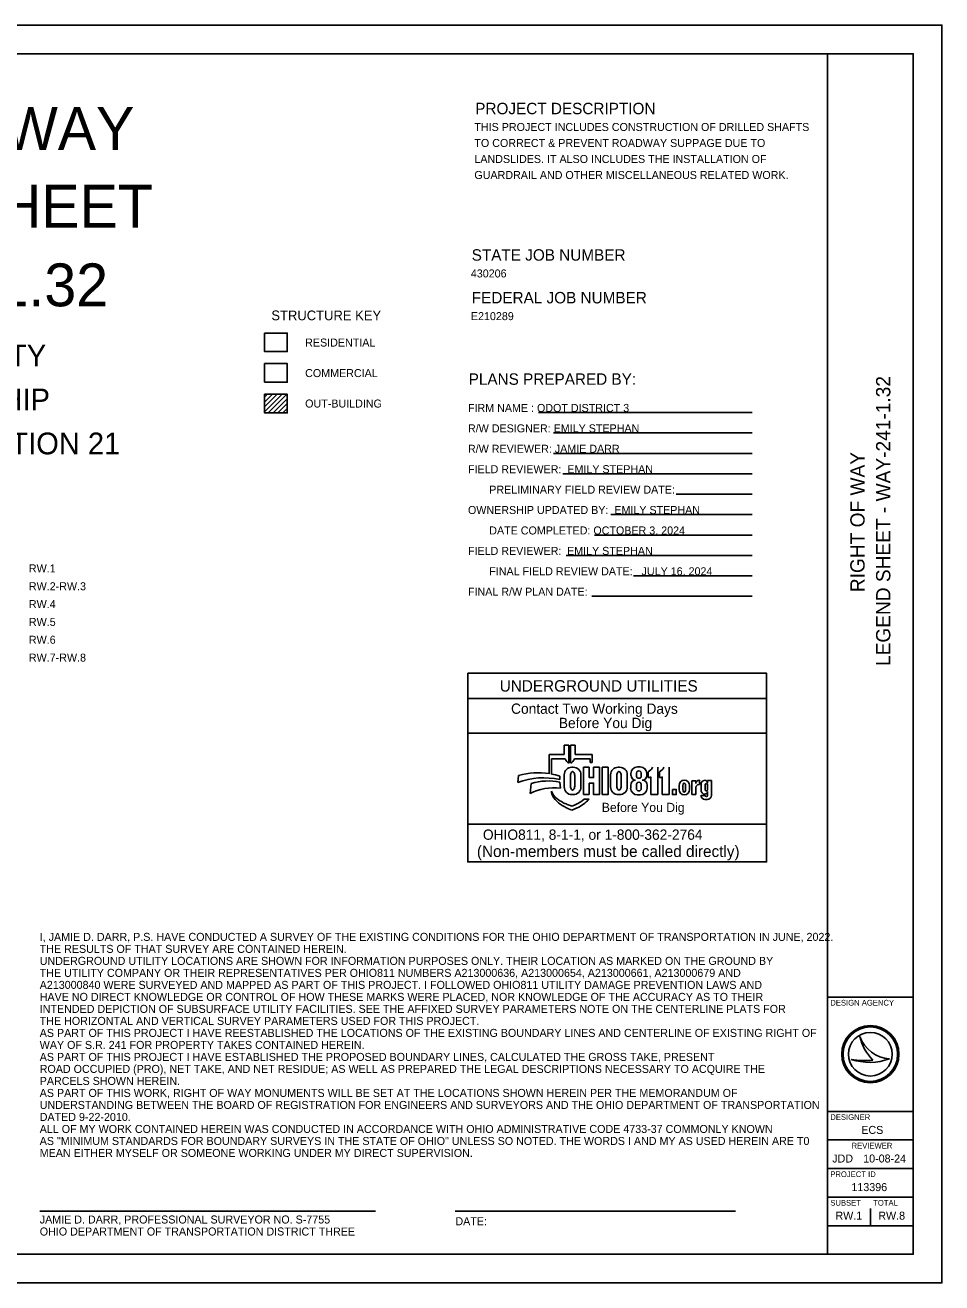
# Model space of a CAD drawing. Extents: x 0 to 34, y 0 to 22.
# Drawn here: x 17.97 to 34, y 0 to 22 of the extents above; entities that cross this region are included whole.
import ezdxf

# ---------------------------------------------------------------- set-up
doc = ezdxf.new("R2010")
doc.units = 0
for name, color, linetype in [('Default', 7, 'Continuous'), ('SC_Shading1', 7, 'Continuous'), ('SH_Border', 7, 'Continuous'), ('SH_Cut_Line', 7, 'Continuous'), ('SH_Data', 7, 'Continuous'), ('SH_Text', 7, 'Continuous')]:
    doc.layers.add(name, color=color, linetype=linetype)

msp = doc.modelspace()

# ---------------------------------------------------------------- linework, layer by layer
at = {"layer": 'Default'}
for p, q in [((18.229, 1.256), (24.096, 1.256)), ((25.492, 1.256), (30.391, 1.256))]:
    msp.add_line(p, q, dxfattribs=at)
at = {"layer": 'SC_Shading1'}
msp.add_lwpolyline([(22.159, 15.753), (22.556, 15.753), (22.556, 16.079), (22.159, 16.079)], close=True, dxfattribs=at)
at = {"layer": 'SH_Border'}
for p, q in [((32, 0.5), (32, 21.5)), ((32, 5), (33.5, 5)), ((32, 3), (33.5, 3)), ((32, 2.5), (33.5, 2.5)), ((32, 2), (33.5, 2)), ((32, 1.5), (33.5, 1.5)), ((32, 1), (33.5, 1))]:
    msp.add_line(p, q, dxfattribs=at)
msp.add_lwpolyline([(1.5, 21.5), (33.5, 21.5), (33.5, 0.5), (1.5, 0.5)], close=True, dxfattribs=at)
at = {"layer": 'SH_Cut_Line'}
msp.add_lwpolyline([(0, 0), (34, 0), (34, 22), (0, 22)], close=True, dxfattribs=at)
at = {"layer": 'SH_Data'}
for p, q in [((27.399, 9.241), (27.136, 9.241)), ((27.136, 9.241), (27.136, 8.906)), ((27.479, 9.407), (27.399, 9.407)), ((27.399, 9.407), (27.399, 9.241)), ((27.479, 9.09), (27.479, 9.407)), ((27.591, 9.407), (27.51, 9.407)), ((27.51, 9.407), (27.51, 9.09)), ((27.591, 9.241), (27.591, 9.407)), ((27.888, 9.241), (27.591, 9.241)), ((27.888, 9.1), (27.888, 9.241)), ((27.174, 8.9), (27.174, 9.164)), ((27.174, 9.164), (27.415, 9.164)), ((27.575, 9.164), (27.853, 9.164)), ((27.853, 9.164), (27.853, 9.1)), ((27.853, 9.1), (27.888, 9.1)), ((28.728, 9.026), (28.679, 9.026)), ((26.601, 8.872), (26.587, 8.755)), ((27.32, 8.804), (27.32, 8.862)), ((27.398, 8.886), (27.398, 8.674)), ((27.507, 8.691), (27.507, 8.873)), ((27.556, 9.019), (27.531, 9.019)), ((27.581, 8.873), (27.581, 8.691)), ((27.69, 8.674), (27.69, 8.886)), ((27.834, 9.018), (27.732, 9.018)), ((27.732, 9.018), (27.732, 8.54)), ((28.209, 8.886), (28.209, 8.674)), ((28.317, 8.691), (28.317, 8.873)), ((28.367, 9.019), (28.342, 9.019)), ((28.392, 8.873), (28.392, 8.691)), ((28.501, 8.674), (28.501, 8.886)), ((28.565, 8.912), (28.565, 8.876)), ((28.664, 8.859), (28.664, 8.917)), ((28.745, 8.917), (28.745, 8.859)), ((28.842, 8.876), (28.842, 8.912)), ((28.865, 8.838), (28.865, 8.939)), ((28.913, 8.54), (28.913, 8.852)), ((29.032, 9.018), (29.032, 8.54)), ((29.065, 8.838), (29.065, 8.939)), ((29.113, 8.54), (29.113, 8.852)), ((29.232, 9.018), (29.232, 8.54)), ((26.822, 8.737), (26.8, 8.557)), ((27.173, 8.6), (27.178, 8.573)), ((27.33, 8.654), (27.321, 8.76)), ((27.834, 8.54), (27.834, 8.742)), ((28.56, 8.706), (28.56, 8.655)), ((28.66, 8.646), (28.66, 8.707)), ((28.745, 8.707), (28.745, 8.646)), ((28.848, 8.655), (28.848, 8.706)), ((29.406, 8.631), (29.406, 8.699)), ((29.473, 8.63), (29.473, 8.699)), ((29.521, 8.699), (29.521, 8.63)), ((29.588, 8.699), (29.588, 8.631)), ((29.701, 8.783), (29.628, 8.783)), ((29.628, 8.783), (29.628, 8.54)), ((29.701, 8.736), (29.701, 8.783)), ((29.701, 8.54), (29.701, 8.667)), ((29.75, 8.717), (29.761, 8.717)), ((29.761, 8.791), (29.755, 8.791)), ((29.761, 8.717), (29.761, 8.791)), ((29.79, 8.618), (29.79, 8.722)), ((29.862, 8.632), (29.862, 8.708)), ((29.904, 8.738), (29.904, 8.785)), ((29.904, 8.785), (29.97, 8.785)), ((29.904, 8.708), (29.904, 8.632)), ((29.904, 8.526), (29.904, 8.596)), ((29.97, 8.785), (29.97, 8.526)), ((27.538, 8.339), (27.449, 8.37)), ((27.531, 8.54), (27.556, 8.54)), ((27.599, 8.366), (27.538, 8.339)), ((27.732, 8.54), (27.834, 8.54)), ((27.832, 8.46), (27.746, 8.46)), ((27.829, 8.457), (27.832, 8.46)), ((28.342, 8.54), (28.367, 8.54)), ((28.68, 8.534), (28.727, 8.534)), ((29.032, 8.54), (28.913, 8.54)), ((29.232, 8.54), (29.113, 8.54)), ((29.628, 8.54), (29.701, 8.54)), ((29.79, 8.526), (29.862, 8.526)), ((29.9, 8.457), (29.859, 8.457)), ((27.473, 8.293), (27.529, 8.269)), ((27.529, 8.269), (27.624, 8.31)), ((30.935, 7.362), (25.71, 7.362)), ((32.567, 4.31), (32.567, 4.31)), ((32.75, 4), (32.75, 4)), ((32.417, 3.91), (32.417, 3.91)), ((33.087, 3.919), (33.087, 3.919)), ((32.75, 1), (32.75, 1.3))]:
    msp.add_line(p, q, dxfattribs=at)
for points in [[(25.71, 10.662), (30.935, 10.662), (30.935, 10.222), (25.71, 10.222)], [(25.71, 10.222), (30.935, 10.222), (30.935, 9.617), (25.71, 9.617)], [(25.71, 9.617), (30.935, 9.617), (30.935, 8.022), (25.71, 8.022)], [(29.29, 8.63), (29.356, 8.63), (29.356, 8.54), (29.29, 8.54)], [(25.71, 8.022), (30.935, 8.022), (30.935, 7.362), (25.71, 7.362)]]:
    msp.add_lwpolyline(points, close=True, dxfattribs=at)
for points in [[(27.834, 8.742), (27.91, 8.742), (27.91, 8.54), (28.012, 8.54), (28.012, 9.018), (27.91, 9.018), (27.91, 8.838), (27.834, 8.838), (27.834, 9.018)], [(28.062, 8.54), (28.165, 8.54), (28.165, 9.018), (28.062, 9.018), (28.062, 8.54)], [(28.646, 8.792), (28.646, 8.792)], [(28.762, 8.792), (28.762, 8.792)]]:
    msp.add_lwpolyline(points, dxfattribs=at)
for radius in [0.5, 0.477, 0.477, 0.382]:
    msp.add_circle((32.75, 4), radius, dxfattribs=at)
for centre, radius, start, end in [((27.551, 9.219), 0.147, 201.9296, 240.7469), ((27.439, 9.219), 0.147, 299.2531, 338.0704), ((28.679, 8.912), 0.114, 90, 180), ((28.728, 8.912), 0.114, 0, 90), ((27.039, 7.502), 1.332, 77.8238, 109.8274), ((26.945, 7.698), 1.224, 81.0007, 106.3144), ((26.945, 7.698), 1.224, 72.1402, 79.2074), ((27.531, 8.886), 0.134, 90, 180), ((27.556, 8.886), 0.134, 0, 90), ((28.342, 8.886), 0.134, 90, 180), ((28.367, 8.886), 0.134, 0, 90), ((28.649, 8.876), 0.0837, 180, 268.1442), ((28.758, 8.876), 0.0837, 272.2058, 0), ((28.814, 9.062), 0.132, 292.5572, 340.7355), ((28.853, 8.969), 0.132, 275.1733, 297.0931), ((29.014, 9.062), 0.132, 292.5572, 340.7355), ((29.053, 8.969), 0.132, 275.1733, 297.0931), ((27.228, 7.71), 0.95, 83.8248, 116.8021), ((27.121, 7.685), 1.094, 79.44, 105.8467), ((27.453, 8.708), 0.3, 201.0457, 232.5314), ((27.531, 8.674), 0.134, 180, 270), ((27.556, 8.674), 0.134, 270, 0), ((28.342, 8.674), 0.134, 180, 270), ((28.367, 8.674), 0.134, 270, 0), ((28.646, 8.706), 0.0865, 90, 180), ((28.68, 8.655), 0.121, 180, 270), ((28.727, 8.655), 0.121, 270, 0), ((28.762, 8.706), 0.0865, 0, 90), ((29.501, 8.699), 0.0956, 92.5886, 180), ((29.501, 8.631), 0.0956, 180, 267.4114), ((29.493, 8.699), 0.0956, 0, 87.4114), ((29.493, 8.631), 0.0956, 272.5886, 0), ((29.755, 8.736), 0.0548, 90, 180), ((29.75, 8.667), 0.0493, 90, 180), ((29.858, 8.722), 0.0686, 92.6865, 180), ((29.859, 8.618), 0.0692, 180, 265.7132), ((29.858, 8.596), 0.0467, 264.7825, 0), ((29.852, 8.738), 0.0524, 0, 86.9262), ((27.389, 8.609), 0.214, 189.6817, 216.0884), ((27.588, 8.755), 0.461, 216.0884, 235.7167), ((27.741, 9.083), 0.773, 232.5314, 241.794), ((27.837, 9.12), 0.903, 235.7167, 246.2325), ((27.613, 8.846), 0.504, 241.794, 250.9821), ((27.385, 8.859), 0.538, 293.4582, 312.0712), ((27.385, 8.859), 0.599, 293.4582, 317.8286), ((29.859, 8.526), 0.0699, 180, 270), ((29.9, 8.526), 0.0699, 270, 0), ((33.116, 4.498), 0.58, 198.9257, 198.9319), ((33.347, 4.47), 0.796, 191.6379, 191.6421), ((33.116, 4.498), 0.58, 198.9319, 267.1657), ((33.347, 4.47), 0.796, 191.6421, 226.0947), ((32.739, 4.87), 1.013, 251.4576, 290.0832), ((32.648, 5.154), 1.266, 259.4964, 259.4995), ((32.739, 4.87), 1.013, 251.4527, 251.4576), ((32.648, 5.154), 1.266, 259.4995, 276.6672)]:
    msp.add_arc(centre, radius, start, end, dxfattribs=at)
for centre, major_axis, ratio, start_param, end_param in [((27.544, 8.873), (0, 0.0723), 0.514403, 4.712389, 7.853982), ((28.355, 8.873), (0, 0.0723), 0.514403, 4.712389, 7.853982), ((28.704, 8.917), (0.0404, 0), 0.969373, 0, 3.141593), ((28.704, 8.859), (0.0404, 0), 0.818453, 3.141593, 6.283185), ((27.544, 8.691), (0, 0.0723), 0.514403, 1.570796, 4.712389), ((28.355, 8.691), (0, 0.0723), 0.514403, 1.570796, 4.712389), ((28.703, 8.707), (0, 0.0535), 0.794529, 4.712389, 7.853982), ((28.703, 8.646), (0.0425, 0), 0.959837, 3.141593, 6.283185), ((29.497, 8.699), (0, 0.0434), 0.553236, 4.712389, 7.853982), ((29.497, 8.63), (0, 0.046), 0.522014, 1.570796, 4.712389), ((29.883, 8.708), (0, 0.0275), 0.777179, 4.712389, 7.853982), ((29.883, 8.632), (0, 0.0275), 0.777179, 1.570796, 4.712389), ((29.883, 8.526), (0.0214, 0), 0.959012, 3.141593, 6.283185)]:
    msp.add_ellipse(centre, major_axis=major_axis, ratio=ratio, start_param=start_param, end_param=end_param, dxfattribs=at)
at = {"layer": 'SH_Text'}
for p, q in [((22.159, 15.542), (22.16, 15.544)), ((22.159, 15.492), (22.211, 15.544)), ((22.159, 15.408), (22.295, 15.544)), ((22.159, 15.323), (22.38, 15.544)), ((22.159, 15.238), (22.465, 15.544)), ((22.224, 15.218), (22.549, 15.544)), ((22.308, 15.218), (22.556, 15.466)), ((22.159, 15.222), (22.164, 15.218)), ((22.393, 15.218), (22.556, 15.381)), ((22.478, 15.218), (22.556, 15.296)), ((26.947, 15.224), (30.684, 15.224)), ((27.211, 14.867), (30.684, 14.867)), ((27.211, 14.51), (30.684, 14.51)), ((27.375, 14.153), (30.684, 14.153)), ((29.356, 13.795), (30.684, 13.795)), ((28.211, 13.439), (30.684, 13.439)), ((27.926, 13.081), (30.684, 13.081)), ((27.429, 12.724), (30.684, 12.724)), ((28.609, 12.367), (30.684, 12.367)), ((27.881, 12.01), (30.684, 12.01))]:
    msp.add_line(p, q, dxfattribs=at)
for points in [[(22.159, 16.614), (22.556, 16.614), (22.556, 16.289), (22.159, 16.289)], [(22.159, 15.544), (22.556, 15.544), (22.556, 15.218), (22.159, 15.218)]]:
    msp.add_lwpolyline(points, close=True, dxfattribs=at)

# ---------------------------------------------------------------- texts
at = {"layer": 'Default'}
for s, height, p in [('PROJECT DESCRIPTION', 0.2, (25.842, 20.442)), ('THIS PROJECT INCLUDES CONSTRUCTION OF DRILLED SHAFTS        ', 0.14, (25.827, 20.149)), ('TO CORRECT & PREVENT ROADWAY SUPPAGE DUE TO', 0.14, (25.827, 19.869)), ('LANDSLIDES. IT ALSO INCLUDES THE INSTALLATION OF            ', 0.14, (25.827, 19.589)), ('GUARDRAIL AND OTHER MISCELLANEOUS RELATED WORK.             ', 0.14, (25.827, 19.309)), ('STATE JOB NUMBER', 0.2, (25.78, 17.88)), ('430206', 0.14, (25.765, 17.587)), ('FEDERAL JOB NUMBER', 0.2, (25.781, 17.133)), ('E210289', 0.14, (25.766, 16.84)), ('I, JAMIE D. DARR, P.S. HAVE CONDUCTED A SURVEY OF THE EXISTING CONDITIONS FOR THE OHIO DEPARTMENT OF TRANSPORTATION IN JUNE, 2022.', 0.14, (18.227, 5.982)), ('THE RESULTS OF THAT SURVEY ARE CONTAINED HEREIN.', 0.14, (18.227, 5.772)), ('UNDERGROUND UTILITY LOCATIONS ARE SHOWN FOR INFORMATION PURPOSES ONLY. THEIR LOCATION AS MARKED ON THE GROUND BY', 0.14, (18.227, 5.562)), ('A213000840 WERE SURVEYED AND MAPPED AS PART OF THIS PROJECT. I FOLLOWED OHIO811 UTILITY DAMAGE PREVENTION LAWS AND', 0.14, (18.227, 5.142)), ('THE UTILITY COMPANY OR THEIR REPRESENTATIVES PER OHIO811 NUMBERS A213000636, A213000654, A213000661, A213000679 AND', 0.14, (18.227, 5.352)), ('HAVE NO DIRECT KNOWLEDGE OR CONTROL OF HOW THESE MARKS WERE PLACED, NOR KNOWLEDGE OF THE ACCURACY AS TO THEIR', 0.14, (18.227, 4.932)), ('INTENDED DEPICTION OF SUBSURFACE UTILITY FACILITIES. SEE THE AFFIXED SURVEY PARAMETERS NOTE ON THE CENTERLINE PLATS FOR', 0.14, (18.227, 4.722)), ('THE HORIZONTAL AND VERTICAL SURVEY PARAMETERS USED FOR THIS PROJECT.', 0.14, (18.227, 4.512)), ('AS PART OF THIS PROJECT I HAVE REESTABLISHED THE LOCATIONS OF THE EXISTING BOUNDARY LINES AND CENTERLINE OF EXISTING RIGHT OF', 0.14, (18.227, 4.302)), ('WAY OF S.R. 241 FOR PROPERTY TAKES CONTAINED HEREIN.', 0.14, (18.227, 4.092)), ('AS PART OF THIS PROJECT I HAVE ESTABLISHED THE PROPOSED BOUNDARY LINES, CALCULATED THE GROSS TAKE, PRESENT', 0.14, (18.227, 3.882)), ('ROAD OCCUPIED (PRO), NET TAKE, AND NET RESIDUE; AS WELL AS PREPARED THE LEGAL DESCRIPTIONS NECESSARY TO ACQUIRE THE', 0.14, (18.227, 3.672)), ('PARCELS SHOWN HEREIN.', 0.14, (18.227, 3.462)), ('AS PART OF THIS WORK, RIGHT OF WAY MONUMENTS WILL BE SET AT THE LOCATIONS SHOWN HEREIN PER THE MEMORANDUM OF', 0.14, (18.227, 3.252)), ('UNDERSTANDING BETWEEN THE BOARD OF REGISTRATION FOR ENGINEERS AND SURVEYORS AND THE OHIO DEPARTMENT OF TRANSPORTATION', 0.14, (18.227, 3.042)), ('DATED 9-22-2010.', 0.14, (18.227, 2.832)), ('ALL OF MY WORK CONTAINED HEREIN WAS CONDUCTED IN ACCORDANCE WITH OHIO ADMINISTRATIVE CODE 4733-37 COMMONLY KNOWN', 0.14, (18.227, 2.622)), ('AS "MINIMUM STANDARDS FOR BOUNDARY SURVEYS IN THE STATE OF OHIO" UNLESS SO NOTED. THE WORDS I AND MY AS USED HEREIN ARE T0', 0.14, (18.227, 2.412)), ('MEAN EITHER MYSELF OR SOMEONE WORKING UNDER MY DIRECT SUPERVISION. ', 0.14, (18.227, 2.202)), ('JAMIE D. DARR, PROFESSIONAL SURVEYOR NO. S-7755', 0.14, (18.228, 1.038)), ('DATE:', 0.14, (25.495, 1.007)), ('OHIO DEPARTMENT OF TRANSPORTATION DISTRICT THREE', 0.14, (18.228, 0.828))]:
    msp.add_text(s, height=height, dxfattribs=at).set_placement(p)
at = {"layer": 'SH_Data'}
for s, height, p in [('RIGHT OF WAY', 0.75, (12.527, 19.816)), ('LEGEND SHEET', 0.75, (12.458, 18.457)), (' WAY-241-1.32', 0.75, (12.567, 17.082)), ('      WAYNE COUNTY     ', 0.38, (13.343, 16.03)), ('     PAINT TOWNSHIP    ', 0.38, (13.325, 15.262)), (' NW QUARTER, SECTION 21', 0.38, (12.774, 14.493)), ('RW.1  ', 0.14, (18.038, 12.427)), ('RW.2-RW.3 ', 0.14, (18.038, 12.115)), ('RW.4  ', 0.14, (18.038, 11.803)), ('RW.5  ', 0.14, (18.038, 11.491)), ('RW.6  ', 0.14, (18.038, 11.179)), ('RW.7-RW.8 ', 0.14, (18.038, 10.867)), ('UNDERGROUND UTILITIES', 0.2, (26.27, 10.342)), ('Contact Two Working Days', 0.18, (26.468, 9.954)), ('Before You Dig', 0.18, (27.303, 9.704)), ('Before You Dig', 0.15972, (28.054, 8.237)), ('OHIO811, 8-1-1, or 1-800-362-2764', 0.18, (25.976, 7.75)), ('(Non-members must be called directly)', 0.2, (25.871, 7.449)), ('DESIGN AGENCY', 0.1, (32.05, 4.85)), ('DESIGNER', 0.1, (32.05, 2.85)), ('ECS', 0.14, (32.592, 2.605)), ('REVIEWER', 0.1, (32.422, 2.35)), ('JDD', 0.14, (32.084, 2.105)), ('10-08-24', 0.14, (32.625, 2.105)), ('PROJECT ID', 0.1, (32.05, 1.85)), ('113396', 0.14, (32.419, 1.605)), ('SUBSET', 0.1, (32.05, 1.35)), ('TOTAL', 0.1, (32.8, 1.35)), ('RW.1', 0.14, (32.14, 1.105)), ('RW.8', 0.14, (32.889, 1.105))]:
    msp.add_text(s, height=height, dxfattribs=at).set_placement(p)
for s, p in [('LEGEND SHEET - WAY-241-1.32', (33.1, 10.79)), ('RIGHT OF WAY', (32.65, 12.082))]:
    msp.add_text(s, height=0.25, rotation=90, dxfattribs=at).set_placement(p)
at = {"layer": 'SH_Text'}
for s, height, p in [('STRUCTURE KEY', 0.17, (22.277, 16.838)), ('RESIDENTIAL', 0.14, (22.868, 16.378)), ('COMMERCIAL', 0.14, (22.868, 15.844)), ('PLANS PREPARED BY:', 0.2, (25.727, 15.709)), ('OUT-BUILDING', 0.14, (22.868, 15.311)), ('FIRM NAME : ODOT DISTRICT 3', 0.14, (25.715, 15.234)), ('R/W DESIGNER: EMILY STEPHAN', 0.14, (25.715, 14.877)), ('R/W REVIEWER: JAMIE DARR', 0.14, (25.715, 14.52)), ('FIELD REVIEWER:  EMILY STEPHAN', 0.14, (25.715, 14.163)), ('PRELIMINARY FIELD REVIEW DATE:', 0.14, (26.087, 13.805)), ('OWNERSHIP UPDATED BY:  EMILY STEPHAN', 0.14, (25.715, 13.449)), ('DATE COMPLETED: OCTOBER 3, 2024', 0.14, (26.087, 13.091)), ('FIELD REVIEWER:', 0.14, (25.715, 12.734)), (' EMILY STEPHAN', 0.14, (27.395, 12.734)), ('FINAL FIELD REVIEW DATE:   JULY 16, 2024', 0.14, (26.087, 12.377)), ('FINAL R/W PLAN DATE:', 0.14, (25.715, 12.02))]:
    msp.add_text(s, height=height, dxfattribs=at).set_placement(p)

doc.saveas('drawing.dxf')
